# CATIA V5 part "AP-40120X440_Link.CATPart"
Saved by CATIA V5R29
Part number: AP-40120X440_Link
Bounding box of the stored display mesh (mm): x -220 to 220, y -60 to 60, z -20 to 20
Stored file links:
  C:\Users\Administrator\Desktop\프로젝트\Boxfold\AP-40120X440_Link.CATPart
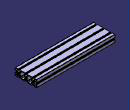
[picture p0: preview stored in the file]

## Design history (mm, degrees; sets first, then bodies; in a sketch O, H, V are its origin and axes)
Body1 (main body)
  Sketch1 on yz-plane, origin (0, 0, 0), H (0, 1, 0), V (0, 0, 1)
    point P1 (-60, -19)
    circle A1 centre (53.5, -13.5) radius 4
    circle A2 centre (53.5, 13.5) radius 4
    circle A3 centre (-53.5, -13.5) radius 4
    circle A4 centre (-53.5, 13.5) radius 4
    arc A5 centre (-38.0088, -3.1185) radius 0.3 from (-37.7966, -2.9064) to (-38.1702, -2.8656) ccw
    line L1 (-37.7966, -2.9064) -> (-37.1018, -3.6012)
    arc A6 centre (-36.8897, -3.3891) radius 0.3 from (-37.1018, -3.6012) to (-36.6868, -3.6101) ccw
    arc A7 centre (-40, 0) radius 4.9 from (-36.6868, -3.6101) to (-36.3857, -3.3086) ccw
    arc A8 centre (-36.607, -3.106) radius 0.3 from (-36.3857, -3.3086) to (-36.3949, -2.8939) ccw
    line L2 (-36.3949, -2.8939) -> (-37.0904, -2.1983)
    arc A9 centre (-36.8783, -1.9862) radius 0.3 from (-37.1314, -1.8252) to (-37.0904, -2.1983) ccw
    arc A10 centre (-40, 0) radius 3.4 from (-37.1314, -1.8252) to (-37.1323, 1.8265) ccw
    arc A11 centre (-36.8792, 1.9877) radius 0.3 from (-37.0914, 2.1998) to (-37.1323, 1.8265) ccw
    line L3 (-37.0914, 2.1998) -> (-36.396, 2.8952)
    arc A12 centre (-36.6081, 3.1073) radius 0.3 from (-36.396, 2.8952) to (-36.3869, 3.31) ccw
    arc A13 centre (-40, 0) radius 4.9 from (-36.3869, 3.31) to (-36.6881, 3.6113) ccw
    arc A14 centre (-36.8909, 3.3902) radius 0.3 from (-36.6881, 3.6113) to (-37.103, 3.6024) ccw
    line L4 (-37.103, 3.6024) -> (-37.7981, 2.9073)
    arc A15 centre (-38.0102, 3.1194) radius 0.3 from (-38.1716, 2.8665) to (-37.7981, 2.9073) ccw
    arc A16 centre (-40, 0) radius 3.4 from (-38.1716, 2.8665) to (-41.8252, 2.8686) ccw
    arc A17 centre (-41.9862, 3.1217) radius 0.3 from (-42.1983, 2.9096) to (-41.8252, 2.8686) ccw
    line L5 (-42.1983, 2.9096) -> (-42.8939, 3.6051)
    arc A18 centre (-43.106, 3.393) radius 0.3 from (-42.8939, 3.6051) to (-43.3086, 3.6143) ccw
    arc A19 centre (-40, 0) radius 4.9 from (-43.3086, 3.6143) to (-43.6101, 3.3132) ccw
    arc A20 centre (-43.3891, 3.1103) radius 0.3 from (-43.6101, 3.3132) to (-43.6012, 2.8982) ccw
    line L6 (-43.6012, 2.8982) -> (-42.9064, 2.2034)
    arc A21 centre (-43.1185, 1.9912) radius 0.3 from (-42.8656, 1.8298) to (-42.9064, 2.2034) ccw
    arc A22 centre (-40, 0) radius 3.4 from (-42.8656, 1.8298) to (-42.8665, -1.8284) ccw
    arc A23 centre (-43.1194, -1.9898) radius 0.3 from (-42.9073, -2.2019) to (-42.8665, -1.8284) ccw
    line L7 (-42.9073, -2.2019) -> (-43.6024, -2.897)
    arc A24 centre (-43.3902, -3.1091) radius 0.3 from (-43.6024, -2.897) to (-43.6113, -3.3119) ccw
    arc A25 centre (-40, 0) radius 4.9 from (-43.6113, -3.3119) to (-43.31, -3.6131) ccw
    arc A26 centre (-43.1073, -3.3919) radius 0.3 from (-43.31, -3.6131) to (-42.8952, -3.604) ccw
    line L8 (-42.8952, -3.604) -> (-42.1998, -2.9086)
    arc A27 centre (-41.9877, -3.1208) radius 0.3 from (-41.8265, -2.8677) to (-42.1998, -2.9086) ccw
    arc A28 centre (-40, 0) radius 3.4 from (-41.8265, -2.8677) to (-38.1702, -2.8656) ccw
    line L9 (39.6951, 6.0049) -> (40, 5.7)
    line L10 (40, 5.7) -> (40.3049, 6.0049)
    arc A29 centre (40, 15.5) radius 9.5 from (40.3049, 6.0049) to (47.0734, 9.1583) ccw
    arc A30 centre (46.85, 9.3585) radius 0.3 from (47.0734, 9.1583) to (47.15, 9.3585) ccw
    line L11 (47.15, 9.3585) -> (47.15, 15.7)
    arc A31 centre (46.85, 15.7) radius 0.3 from (47.15, 15.7) to (46.85, 16) ccw
    line L12 (46.85, 16) -> (44.65, 16)
    arc A32 centre (44.65, 16.5) radius 0.5 from (44.15, 16.5) to (44.65, 16) ccw
    line L13 (44.15, 16.5) -> (44.15, 19.5)
    arc A33 centre (44.65, 19.5) radius 0.5 from (44.65, 20) to (44.15, 19.5) ccw
    line L14 (44.65, 20) -> (59, 20)
    arc A34 centre (59, 19) radius 1 from (60, 19) to (59, 20) ccw
    line L15 (60, 19) -> (60, 4.65)
    arc A35 centre (59.5, 4.65) radius 0.5 from (59.5, 4.15) to (60, 4.65) ccw
    line L16 (59.5, 4.15) -> (56.5, 4.15)
    arc A36 centre (56.5, 4.65) radius 0.5 from (56, 4.65) to (56.5, 4.15) ccw
    line L17 (56, 4.65) -> (56, 6.85)
    arc A37 centre (55.7, 6.85) radius 0.3 from (56, 6.85) to (55.7, 7.15) ccw
    line L18 (55.7, 7.15) -> (49.3585, 7.15)
    arc A38 centre (49.3585, 6.85) radius 0.3 from (49.3585, 7.15) to (49.1583, 7.0734) ccw
    arc A39 centre (55.5, 0) radius 9.5 from (49.1583, 7.0734) to (46.0049, 0.3049) ccw
    line L19 (46.0049, 0.3049) -> (45.7, 0)
    line L20 (45.7, 0) -> (46.0049, -0.3049)
    arc A40 centre (55.5, 0) radius 9.5 from (46.0049, -0.3049) to (49.1583, -7.0734) ccw
    arc A41 centre (49.3585, -6.85) radius 0.3 from (49.1583, -7.0734) to (49.3585, -7.15) ccw
    line L21 (49.3585, -7.15) -> (55.7, -7.15)
    arc A42 centre (55.7, -6.85) radius 0.3 from (55.7, -7.15) to (56, -6.85) ccw
    line L22 (56, -6.85) -> (56, -4.65)
    arc A43 centre (56.5, -4.65) radius 0.5 from (56.5, -4.15) to (56, -4.65) ccw
    line L23 (56.5, -4.15) -> (59.5, -4.15)
    arc A44 centre (59.5, -4.65) radius 0.5 from (60, -4.65) to (59.5, -4.15) ccw
    line L24 (60, -4.65) -> (60, -19)
    arc A45 centre (59, -19) radius 1 from (59, -20) to (60, -19) ccw
    line L25 (59, -20) -> (44.65, -20)
    arc A46 centre (44.65, -19.5) radius 0.5 from (44.15, -19.5) to (44.65, -20) ccw
    line L26 (44.15, -19.5) -> (44.15, -16.5)
    arc A47 centre (44.65, -16.5) radius 0.5 from (44.65, -16) to (44.15, -16.5) ccw
    line L27 (44.65, -16) -> (46.85, -16)
    arc A48 centre (46.85, -15.7) radius 0.3 from (46.85, -16) to (47.15, -15.7) ccw
    line L28 (47.15, -15.7) -> (47.15, -9.3585)
    arc A49 centre (46.85, -9.3585) radius 0.3 from (47.15, -9.3585) to (47.0734, -9.1583) ccw
    arc A50 centre (40, -15.5) radius 9.5 from (47.0734, -9.1583) to (40.3049, -6.0049) ccw
    line L29 (40.3049, -6.0049) -> (40, -5.7)
    line L30 (40, -5.7) -> (39.6951, -6.0049)
    arc A51 centre (40, -15.5) radius 9.5 from (39.6951, -6.0049) to (32.9266, -9.1583) ccw
    arc A52 centre (33.15, -9.3585) radius 0.3 from (32.9266, -9.1583) to (32.85, -9.3585) ccw
    line L31 (32.85, -9.3585) -> (32.85, -15.7)
    arc A53 centre (33.15, -15.7) radius 0.3 from (32.85, -15.7) to (33.15, -16) ccw
    line L32 (33.15, -16) -> (35.35, -16)
    arc A54 centre (35.35, -16.5) radius 0.5 from (35.85, -16.5) to (35.35, -16) ccw
    line L33 (35.85, -16.5) -> (35.85, -19.5)
    arc A55 centre (35.35, -19.5) radius 0.5 from (35.35, -20) to (35.85, -19.5) ccw
    line L34 (35.35, -20) -> (4.65, -20)
    arc A56 centre (4.65, -19.5) radius 0.5 from (4.15, -19.5) to (4.65, -20) ccw
    line L35 (4.15, -19.5) -> (4.15, -16.5)
    arc A57 centre (4.65, -16.5) radius 0.5 from (4.65, -16) to (4.15, -16.5) ccw
    line L36 (4.65, -16) -> (6.85, -16)
    arc A58 centre (6.85, -15.7) radius 0.3 from (6.85, -16) to (7.15, -15.7) ccw
    line L37 (7.15, -15.7) -> (7.15, -9.3585)
    arc A59 centre (6.85, -9.3585) radius 0.3 from (7.15, -9.3585) to (7.0734, -9.1583) ccw
    arc A60 centre (0, -15.5) radius 9.5 from (7.0734, -9.1583) to (0.3049, -6.0049) ccw
    line L38 (0.3049, -6.0049) -> (0, -5.7)
    line L39 (0, -5.7) -> (-0.3049, -6.0049)
    arc A61 centre (0, -15.5) radius 9.5 from (-0.3049, -6.0049) to (-7.0734, -9.1583) ccw
    arc A62 centre (-6.85, -9.3585) radius 0.3 from (-7.0734, -9.1583) to (-7.15, -9.3585) ccw
    line L40 (-7.15, -9.3585) -> (-7.15, -15.7)
    arc A63 centre (-6.85, -15.7) radius 0.3 from (-7.15, -15.7) to (-6.85, -16) ccw
    line L41 (-6.85, -16) -> (-4.65, -16)
    arc A64 centre (-4.65, -16.5) radius 0.5 from (-4.15, -16.5) to (-4.65, -16) ccw
    line L42 (-4.15, -16.5) -> (-4.15, -19.5)
    arc A65 centre (-4.65, -19.5) radius 0.5 from (-4.65, -20) to (-4.15, -19.5) ccw
    line L43 (-4.65, -20) -> (-35.35, -20)
    arc A66 centre (-35.35, -19.5) radius 0.5 from (-35.85, -19.5) to (-35.35, -20) ccw
    line L44 (-35.85, -19.5) -> (-35.85, -16.5)
    arc A67 centre (-35.35, -16.5) radius 0.5 from (-35.35, -16) to (-35.85, -16.5) ccw
    line L45 (-35.35, -16) -> (-33.15, -16)
    arc A68 centre (-33.15, -15.7) radius 0.3 from (-33.15, -16) to (-32.85, -15.7) ccw
    line L46 (-32.85, -15.7) -> (-32.85, -9.3585)
    arc A69 centre (-33.15, -9.3585) radius 0.3 from (-32.85, -9.3585) to (-32.9266, -9.1583) ccw
    arc A70 centre (-40, -15.5) radius 9.5 from (-32.9266, -9.1583) to (-39.6951, -6.0049) ccw
    line L47 (-39.6951, -6.0049) -> (-40, -5.7)
    line L48 (-40, -5.7) -> (-40.3049, -6.0049)
    arc A71 centre (-40, -15.5) radius 9.5 from (-40.3049, -6.0049) to (-47.0734, -9.1583) ccw
    arc A72 centre (-46.85, -9.3585) radius 0.3 from (-47.0734, -9.1583) to (-47.15, -9.3585) ccw
    line L49 (-47.15, -9.3585) -> (-47.15, -15.7)
    arc A73 centre (-46.85, -15.7) radius 0.3 from (-47.15, -15.7) to (-46.85, -16) ccw
    line L50 (-46.85, -16) -> (-44.65, -16)
    arc A74 centre (-44.65, -16.5) radius 0.5 from (-44.15, -16.5) to (-44.65, -16) ccw
    line L51 (-44.15, -16.5) -> (-44.15, -19.5)
    arc A75 centre (-44.65, -19.5) radius 0.5 from (-44.65, -20) to (-44.15, -19.5) ccw
    line L52 (-44.65, -20) -> (-58, -20)
    line L53 (-58, -20) -> (-59, -20)
    arc A76 centre (-59, -19) radius 1 from (-60, -19) to (-59, -20) ccw
    line L54 (-60, -19) -> (-60, -4.65)
    arc A77 centre (-59.5, -4.65) radius 0.5 from (-59.5, -4.15) to (-60, -4.65) ccw
    line L55 (-59.5, -4.15) -> (-56.5, -4.15)
    arc A78 centre (-56.5, -4.65) radius 0.5 from (-56, -4.65) to (-56.5, -4.15) ccw
    line L56 (-56, -4.65) -> (-56, -6.85)
    arc A79 centre (-55.7, -6.85) radius 0.3 from (-56, -6.85) to (-55.7, -7.15) ccw
    line L57 (-55.7, -7.15) -> (-49.3585, -7.15)
    arc A80 centre (-49.3585, -6.85) radius 0.3 from (-49.3585, -7.15) to (-49.1583, -7.0734) ccw
    arc A81 centre (-55.5, 0) radius 9.5 from (-49.1583, -7.0734) to (-46.0049, -0.3049) ccw
    line L58 (-46.0049, -0.3049) -> (-45.7, 0)
    line L59 (-45.7, 0) -> (-46.0049, 0.3049)
    arc A82 centre (-55.5, 0) radius 9.5 from (-46.0049, 0.3049) to (-49.1583, 7.0734) ccw
    arc A83 centre (-49.3585, 6.85) radius 0.3 from (-49.1583, 7.0734) to (-49.3585, 7.15) ccw
    line L60 (-49.3585, 7.15) -> (-55.7, 7.15)
    arc A84 centre (-55.7, 6.85) radius 0.3 from (-55.7, 7.15) to (-56, 6.85) ccw
    line L61 (-56, 6.85) -> (-56, 4.65)
    arc A85 centre (-56.5, 4.65) radius 0.5 from (-56.5, 4.15) to (-56, 4.65) ccw
    line L62 (-56.5, 4.15) -> (-59.5, 4.15)
    arc A86 centre (-59.5, 4.65) radius 0.5 from (-60, 4.65) to (-59.5, 4.15) ccw
    line L63 (-60, 4.65) -> (-60, 19)
    arc A87 centre (-59, 19) radius 1 from (-59, 20) to (-60, 19) ccw
    line L64 (-59, 20) -> (-58, 20)
    line L65 (-58, 20) -> (-44.65, 20)
    arc A88 centre (-44.65, 19.5) radius 0.5 from (-44.15, 19.5) to (-44.65, 20) ccw
    line L66 (-44.15, 19.5) -> (-44.15, 16.5)
    arc A89 centre (-44.65, 16.5) radius 0.5 from (-44.65, 16) to (-44.15, 16.5) ccw
    line L67 (-44.65, 16) -> (-46.85, 16)
    arc A90 centre (-46.85, 15.7) radius 0.3 from (-46.85, 16) to (-47.15, 15.7) ccw
    line L68 (-47.15, 15.7) -> (-47.15, 9.3585)
    arc A91 centre (-46.85, 9.3585) radius 0.3 from (-47.15, 9.3585) to (-47.0734, 9.1583) ccw
    arc A92 centre (-40, 15.5) radius 9.5 from (-47.0734, 9.1583) to (-40.3049, 6.0049) ccw
    line L69 (-40.3049, 6.0049) -> (-40, 5.7)
    line L70 (-40, 5.7) -> (-39.6951, 6.0049)
    arc A93 centre (-40, 15.5) radius 9.5 from (-39.6951, 6.0049) to (-32.9266, 9.1583) ccw
    arc A94 centre (-33.15, 9.3585) radius 0.3 from (-32.9266, 9.1583) to (-32.85, 9.3585) ccw
    line L71 (-32.85, 9.3585) -> (-32.85, 15.7)
    arc A95 centre (-33.15, 15.7) radius 0.3 from (-32.85, 15.7) to (-33.15, 16) ccw
    line L72 (-33.15, 16) -> (-35.35, 16)
    arc A96 centre (-35.35, 16.5) radius 0.5 from (-35.85, 16.5) to (-35.35, 16) ccw
    line L73 (-35.85, 16.5) -> (-35.85, 19.5)
    arc A97 centre (-35.35, 19.5) radius 0.5 from (-35.35, 20) to (-35.85, 19.5) ccw
    line L74 (-35.35, 20) -> (-4.65, 20)
    arc A98 centre (-4.65, 19.5) radius 0.5 from (-4.15, 19.5) to (-4.65, 20) ccw
    line L75 (-4.15, 19.5) -> (-4.15, 16.5)
    arc A99 centre (-4.65, 16.5) radius 0.5 from (-4.65, 16) to (-4.15, 16.5) ccw
    line L76 (-4.65, 16) -> (-6.85, 16)
    arc A100 centre (-6.85, 15.7) radius 0.3 from (-6.85, 16) to (-7.15, 15.7) ccw
    line L77 (-7.15, 15.7) -> (-7.15, 9.3585)
    arc A101 centre (-6.85, 9.3585) radius 0.3 from (-7.15, 9.3585) to (-7.0734, 9.1583) ccw
    arc A102 centre (0, 15.5) radius 9.5 from (-7.0734, 9.1583) to (-0.3049, 6.0049) ccw
    line L78 (-0.3049, 6.0049) -> (0, 5.7)
    line L79 (0, 5.7) -> (0.3049, 6.0049)
    arc A103 centre (0, 15.5) radius 9.5 from (0.3049, 6.0049) to (7.0734, 9.1583) ccw
    arc A104 centre (6.85, 9.3585) radius 0.3 from (7.0734, 9.1583) to (7.15, 9.3585) ccw
    line L80 (7.15, 9.3585) -> (7.15, 15.7)
    arc A105 centre (6.85, 15.7) radius 0.3 from (7.15, 15.7) to (6.85, 16) ccw
    line L81 (6.85, 16) -> (4.65, 16)
    arc A106 centre (4.65, 16.5) radius 0.5 from (4.15, 16.5) to (4.65, 16) ccw
    line L82 (4.15, 16.5) -> (4.15, 19.5)
    arc A107 centre (4.65, 19.5) radius 0.5 from (4.65, 20) to (4.15, 19.5) ccw
    line L83 (4.65, 20) -> (35.35, 20)
    arc A108 centre (35.35, 19.5) radius 0.5 from (35.85, 19.5) to (35.35, 20) ccw
    line L84 (35.85, 19.5) -> (35.85, 16.5)
    arc A109 centre (35.35, 16.5) radius 0.5 from (35.35, 16) to (35.85, 16.5) ccw
    line L85 (35.35, 16) -> (33.15, 16)
    arc A110 centre (33.15, 15.7) radius 0.3 from (33.15, 16) to (32.85, 15.7) ccw
    line L86 (32.85, 15.7) -> (32.85, 9.3585)
    arc A111 centre (33.15, 9.3585) radius 0.3 from (32.85, 9.3585) to (32.9266, 9.1583) ccw
    arc A112 centre (40, 15.5) radius 9.5 from (32.9266, 9.1583) to (39.6951, 6.0049) ccw
    arc A113 centre (13.15, -14) radius 3 from (10.15, -14) to (13.15, -17) ccw
    line L87 (13.15, -17) -> (26.85, -17)
    arc A114 centre (26.85, -14) radius 3 from (26.85, -17) to (29.85, -14) ccw
    line L88 (29.85, -14) -> (29.85, -8.9422)
    arc A115 centre (20, -0.0053) radius 13.3 from (29.85, -8.9422) to (29.85, 8.9315) ccw
    line L89 (29.85, 8.9315) -> (29.85, 14)
    arc A116 centre (26.85, 14) radius 3 from (29.85, 14) to (26.85, 17) ccw
    line L90 (26.85, 17) -> (13.15, 17)
    arc A117 centre (13.15, 14) radius 3 from (13.15, 17) to (10.15, 14) ccw
    line L91 (10.15, 14) -> (10.15, 8.9315)
    arc A118 centre (20, -0.0053) radius 13.3 from (10.15, 8.9315) to (10.15, -8.9422) ccw
    line L92 (10.15, -8.9422) -> (10.15, -14)
    arc A119 centre (1.9912, -3.1185) radius 0.3 from (2.2034, -2.9064) to (1.8298, -2.8656) ccw
    line L93 (2.2034, -2.9064) -> (2.8982, -3.6012)
    arc A120 centre (3.1103, -3.3891) radius 0.3 from (2.8982, -3.6012) to (3.3132, -3.6101) ccw
    arc A121 centre (0, 0) radius 4.9 from (3.3132, -3.6101) to (3.6143, -3.3086) ccw
    arc A122 centre (3.393, -3.106) radius 0.3 from (3.6143, -3.3086) to (3.6051, -2.8939) ccw
    line L94 (3.6051, -2.8939) -> (2.9096, -2.1983)
    arc A123 centre (3.1217, -1.9862) radius 0.3 from (2.8686, -1.8252) to (2.9096, -2.1983) ccw
    arc A124 centre (0, 0) radius 3.4 from (2.8686, -1.8252) to (2.8677, 1.8265) ccw
    arc A125 centre (3.1208, 1.9877) radius 0.3 from (2.9086, 2.1998) to (2.8677, 1.8265) ccw
    line L95 (2.9086, 2.1998) -> (3.604, 2.8952)
    arc A126 centre (3.3919, 3.1073) radius 0.3 from (3.604, 2.8952) to (3.6131, 3.31) ccw
    arc A127 centre (0, 0) radius 4.9 from (3.6131, 3.31) to (3.3119, 3.6113) ccw
    arc A128 centre (3.1091, 3.3902) radius 0.3 from (3.3119, 3.6113) to (2.897, 3.6024) ccw
    line L96 (2.897, 3.6024) -> (2.2019, 2.9073)
    arc A129 centre (1.9898, 3.1194) radius 0.3 from (1.8284, 2.8665) to (2.2019, 2.9073) ccw
    arc A130 centre (0, 0) radius 3.4 from (1.8284, 2.8665) to (-1.8252, 2.8686) ccw
    arc A131 centre (-1.9862, 3.1217) radius 0.3 from (-2.1983, 2.9096) to (-1.8252, 2.8686) ccw
    line L97 (-2.1983, 2.9096) -> (-2.8939, 3.6051)
    arc A132 centre (-3.106, 3.393) radius 0.3 from (-2.8939, 3.6051) to (-3.3086, 3.6143) ccw
    arc A133 centre (0, 0) radius 4.9 from (-3.3086, 3.6143) to (-3.6101, 3.3132) ccw
    arc A134 centre (-3.3891, 3.1103) radius 0.3 from (-3.6101, 3.3132) to (-3.6012, 2.8982) ccw
    line L98 (-3.6012, 2.8982) -> (-2.9064, 2.2034)
    arc A135 centre (-3.1185, 1.9912) radius 0.3 from (-2.8656, 1.8298) to (-2.9064, 2.2034) ccw
    arc A136 centre (0, 0) radius 3.4 from (-2.8656, 1.8298) to (-2.8665, -1.8284) ccw
    arc A137 centre (-3.1194, -1.9898) radius 0.3 from (-2.9073, -2.2019) to (-2.8665, -1.8284) ccw
    line L99 (-2.9073, -2.2019) -> (-3.6024, -2.897)
    arc A138 centre (-3.3902, -3.1091) radius 0.3 from (-3.6024, -2.897) to (-3.6113, -3.3119) ccw
    arc A139 centre (0, 0) radius 4.9 from (-3.6113, -3.3119) to (-3.31, -3.6131) ccw
    arc A140 centre (-3.1073, -3.3919) radius 0.3 from (-3.31, -3.6131) to (-2.8952, -3.604) ccw
    line L100 (-2.8952, -3.604) -> (-2.1998, -2.9086)
    arc A141 centre (-1.9877, -3.1208) radius 0.3 from (-1.8265, -2.8677) to (-2.1998, -2.9086) ccw
    arc A142 centre (0, 0) radius 3.4 from (-1.8265, -2.8677) to (1.8298, -2.8656) ccw
    arc A143 centre (41.9912, -3.1185) radius 0.3 from (42.2034, -2.9064) to (41.8298, -2.8656) ccw
    line L101 (42.2034, -2.9064) -> (42.8982, -3.6012)
    arc A144 centre (43.1103, -3.3891) radius 0.3 from (42.8982, -3.6012) to (43.3132, -3.6101) ccw
    arc A145 centre (40, 0) radius 4.9 from (43.3132, -3.6101) to (43.6143, -3.3086) ccw
    arc A146 centre (43.393, -3.106) radius 0.3 from (43.6143, -3.3086) to (43.6051, -2.8939) ccw
    line L102 (43.6051, -2.8939) -> (42.9096, -2.1983)
    arc A147 centre (43.1217, -1.9862) radius 0.3 from (42.8686, -1.8252) to (42.9096, -2.1983) ccw
    arc A148 centre (40, 0) radius 3.4 from (42.8686, -1.8252) to (42.8677, 1.8265) ccw
    arc A149 centre (43.1208, 1.9877) radius 0.3 from (42.9086, 2.1998) to (42.8677, 1.8265) ccw
    line L103 (42.9086, 2.1998) -> (43.604, 2.8952)
    arc A150 centre (43.3919, 3.1073) radius 0.3 from (43.604, 2.8952) to (43.6131, 3.31) ccw
    arc A151 centre (40, 0) radius 4.9 from (43.6131, 3.31) to (43.3119, 3.6113) ccw
    arc A152 centre (43.1091, 3.3902) radius 0.3 from (43.3119, 3.6113) to (42.897, 3.6024) ccw
    line L104 (42.897, 3.6024) -> (42.2019, 2.9073)
    arc A153 centre (41.9898, 3.1194) radius 0.3 from (41.8284, 2.8665) to (42.2019, 2.9073) ccw
    arc A154 centre (40, 0) radius 3.4 from (41.8284, 2.8665) to (38.1748, 2.8686) ccw
    arc A155 centre (38.0138, 3.1217) radius 0.3 from (37.8017, 2.9096) to (38.1748, 2.8686) ccw
    line L105 (37.8017, 2.9096) -> (37.1061, 3.6051)
    arc A156 centre (36.894, 3.393) radius 0.3 from (37.1061, 3.6051) to (36.6914, 3.6143) ccw
    arc A157 centre (40, 0) radius 4.9 from (36.6914, 3.6143) to (36.3899, 3.3132) ccw
    arc A158 centre (36.6109, 3.1103) radius 0.3 from (36.3899, 3.3132) to (36.3988, 2.8982) ccw
    line L106 (36.3988, 2.8982) -> (37.0936, 2.2034)
    arc A159 centre (36.8815, 1.9912) radius 0.3 from (37.1344, 1.8298) to (37.0936, 2.2034) ccw
    arc A160 centre (40, 0) radius 3.4 from (37.1344, 1.8298) to (37.1335, -1.8284) ccw
    arc A161 centre (36.8806, -1.9898) radius 0.3 from (37.0927, -2.2019) to (37.1335, -1.8284) ccw
    line L107 (37.0927, -2.2019) -> (36.3976, -2.897)
    arc A162 centre (36.6098, -3.1091) radius 0.3 from (36.3976, -2.897) to (36.3887, -3.3119) ccw
    arc A163 centre (40, 0) radius 4.9 from (36.3887, -3.3119) to (36.69, -3.6131) ccw
    arc A164 centre (36.8927, -3.3919) radius 0.3 from (36.69, -3.6131) to (37.1048, -3.604) ccw
    line L108 (37.1048, -3.604) -> (37.8002, -2.9086)
    arc A165 centre (38.0123, -3.1208) radius 0.3 from (38.1735, -2.8677) to (37.8002, -2.9086) ccw
    arc A166 centre (40, 0) radius 3.4 from (38.1735, -2.8677) to (41.8298, -2.8656) ccw
    line L109 (-13.15, 17) -> (-26.85, 17)
    arc A167 centre (-26.85, 14) radius 3 from (-26.85, 17) to (-29.85, 14) ccw
    line L110 (-29.85, 14) -> (-29.85, 8.9315)
    arc A168 centre (-20, -0.0053) radius 13.3 from (-29.85, 8.9315) to (-29.85, -8.9422) ccw
    line L111 (-29.85, -8.9422) -> (-29.85, -14)
    arc A169 centre (-26.85, -14) radius 3 from (-29.85, -14) to (-26.85, -17) ccw
    line L112 (-26.85, -17) -> (-13.15, -17)
    arc A170 centre (-13.15, -14) radius 3 from (-13.15, -17) to (-10.15, -14) ccw
    line L113 (-10.15, -14) -> (-10.15, -8.9422)
    arc A171 centre (-20, -0.0053) radius 13.3 from (-10.15, -8.9422) to (-10.15, 8.9315) ccw
    line L114 (-10.15, 8.9315) -> (-10.15, 14)
    arc A172 centre (-13.15, 14) radius 3 from (-10.15, 14) to (-13.15, 17) ccw
    point P2 (-37.7966, -2.9064)
    point P3 (-38.1702, -2.8656)
    point P4 (-37.7966, -2.9064)
    point P5 (-37.1018, -3.6012)
    point P6 (-37.1018, -3.6012)
    point P7 (-36.6868, -3.6101)
    point P8 (-36.6868, -3.6101)
    point P9 (-36.3857, -3.3086)
    point P10 (-36.3857, -3.3086)
    point P11 (-36.3949, -2.8939)
    point P12 (-36.3949, -2.8939)
    point P13 (-37.0904, -2.1983)
    point P14 (-37.1314, -1.8252)
    point P15 (-37.0904, -2.1983)
    point P16 (-37.1314, -1.8252)
    point P17 (-37.1323, 1.8265)
    point P18 (-37.0914, 2.1998)
    point P19 (-37.1323, 1.8265)
    point P20 (-37.0914, 2.1998)
    point P21 (-36.396, 2.8952)
    point P22 (-36.396, 2.8952)
    point P23 (-36.3869, 3.31)
    point P24 (-36.3869, 3.31)
    point P25 (-36.6881, 3.6113)
    point P26 (-36.6881, 3.6113)
    point P27 (-37.103, 3.6024)
    point P28 (-37.103, 3.6024)
    point P29 (-37.7981, 2.9073)
    point P30 (-38.1716, 2.8665)
    point P31 (-37.7981, 2.9073)
    point P32 (-38.1716, 2.8665)
    point P33 (-41.8252, 2.8686)
    point P34 (-42.1983, 2.9096)
    point P35 (-41.8252, 2.8686)
    point P36 (-42.1983, 2.9096)
    point P37 (-42.8939, 3.6051)
    point P38 (-42.8939, 3.6051)
    point P39 (-43.3086, 3.6143)
    point P40 (-43.3086, 3.6143)
    point P41 (-43.6101, 3.3132)
    point P42 (-43.6101, 3.3132)
    point P43 (-43.6012, 2.8982)
    point P44 (-43.6012, 2.8982)
    point P45 (-42.9064, 2.2034)
    point P46 (-42.8656, 1.8298)
    point P47 (-42.9064, 2.2034)
    point P48 (-42.8656, 1.8298)
    point P49 (-42.8665, -1.8284)
    point P50 (-42.9073, -2.2019)
    point P51 (-42.8665, -1.8284)
    point P52 (-42.9073, -2.2019)
    point P53 (-43.6024, -2.897)
    point P54 (-43.6024, -2.897)
    point P55 (-43.6113, -3.3119)
    point P56 (-43.6113, -3.3119)
    point P57 (-43.31, -3.6131)
    point P58 (-43.31, -3.6131)
    point P59 (-42.8952, -3.604)
    point P60 (-42.8952, -3.604)
    point P61 (-42.1998, -2.9086)
    point P62 (-41.8265, -2.8677)
    point P63 (-42.1998, -2.9086)
    point P64 (-41.8265, -2.8677)
    point P65 (-38.1702, -2.8656)
    point P66 (39.6951, 6.0049)
    point P67 (40, 5.7)
    point P68 (40, 5.7)
    point P69 (40.3049, 6.0049)
    point P70 (40.3049, 6.0049)
    point P71 (47.0734, 9.1583)
    point P72 (47.0734, 9.1583)
    point P73 (47.15, 9.3585)
    point P74 (47.15, 9.3585)
    point P75 (47.15, 15.7)
    point P76 (47.15, 15.7)
    point P77 (46.85, 16)
    point P78 (46.85, 16)
    point P79 (44.65, 16)
    point P80 (44.15, 16.5)
    point P81 (44.65, 16)
    point P82 (44.15, 16.5)
    point P83 (44.15, 19.5)
    point P84 (44.65, 20)
    point P85 (44.15, 19.5)
    point P86 (44.65, 20)
    point P87 (59, 20)
    point P88 (60, 19)
    point P89 (59, 20)
    point P90 (60, 19)
    point P91 (60, 4.65)
    point P92 (59.5, 4.15)
    point P93 (60, 4.65)
    point P94 (59.5, 4.15)
    point P95 (56.5, 4.15)
    point P96 (56, 4.65)
    point P97 (56.5, 4.15)
    point P98 (56, 4.65)
    point P99 (56, 6.85)
    point P100 (56, 6.85)
    point P101 (55.7, 7.15)
    point P102 (55.7, 7.15)
    point P103 (49.3585, 7.15)
    point P104 (49.3585, 7.15)
    point P105 (49.1583, 7.0734)
    point P106 (49.1583, 7.0734)
    point P107 (46.0049, 0.3049)
    point P108 (46.0049, 0.3049)
    point P109 (45.7, 0)
    point P110 (45.7, 0)
    point P111 (46.0049, -0.3049)
    point P112 (46.0049, -0.3049)
    point P113 (49.1583, -7.0734)
    point P114 (49.1583, -7.0734)
    point P115 (49.3585, -7.15)
    point P116 (49.3585, -7.15)
    point P117 (55.7, -7.15)
    point P118 (55.7, -7.15)
    point P119 (56, -6.85)
    point P120 (56, -6.85)
    point P121 (56, -4.65)
    point P122 (56.5, -4.15)
    point P123 (56, -4.65)
    point P124 (56.5, -4.15)
    point P125 (59.5, -4.15)
    point P126 (60, -4.65)
    point P127 (59.5, -4.15)
    point P128 (60, -4.65)
    point P129 (60, -19)
    point P130 (59, -20)
    point P131 (60, -19)
    point P132 (59, -20)
    point P133 (44.65, -20)
    point P134 (44.15, -19.5)
    point P135 (44.65, -20)
    point P136 (44.15, -19.5)
    point P137 (44.15, -16.5)
    point P138 (44.65, -16)
    point P139 (44.15, -16.5)
    point P140 (44.65, -16)
    point P141 (46.85, -16)
    point P142 (46.85, -16)
    point P143 (47.15, -15.7)
    point P144 (47.15, -15.7)
    point P145 (47.15, -9.3585)
    point P146 (47.15, -9.3585)
    point P147 (47.0734, -9.1583)
    point P148 (47.0734, -9.1583)
    point P149 (40.3049, -6.0049)
    point P150 (40.3049, -6.0049)
    point P151 (40, -5.7)
    point P152 (40, -5.7)
    point P153 (39.6951, -6.0049)
    point P154 (39.6951, -6.0049)
    point P155 (32.9266, -9.1583)
    point P156 (32.9266, -9.1583)
    point P157 (32.85, -9.3585)
    point P158 (32.85, -9.3585)
    point P159 (32.85, -15.7)
    point P160 (32.85, -15.7)
    point P161 (33.15, -16)
    point P162 (33.15, -16)
    point P163 (35.35, -16)
    point P164 (35.85, -16.5)
    point P165 (35.35, -16)
    point P166 (35.85, -16.5)
    point P167 (35.85, -19.5)
    point P168 (35.35, -20)
    point P169 (35.85, -19.5)
    point P170 (35.35, -20)
    point P171 (4.65, -20)
    point P172 (4.15, -19.5)
    point P173 (4.65, -20)
    point P174 (4.15, -19.5)
    point P175 (4.15, -16.5)
    point P176 (4.65, -16)
    point P177 (4.15, -16.5)
    point P178 (4.65, -16)
    point P179 (6.85, -16)
    point P180 (6.85, -16)
    point P181 (7.15, -15.7)
    point P182 (7.15, -15.7)
    point P183 (7.15, -9.3585)
    point P184 (7.15, -9.3585)
    point P185 (7.0734, -9.1583)
    point P186 (7.0734, -9.1583)
    point P187 (0.3049, -6.0049)
    point P188 (0.3049, -6.0049)
    point P189 (0, -5.7)
    point P190 (0, -5.7)
    point P191 (-0.3049, -6.0049)
    point P192 (-0.3049, -6.0049)
    point P193 (-7.0734, -9.1583)
    point P194 (-7.0734, -9.1583)
    point P195 (-7.15, -9.3585)
    point P196 (-7.15, -9.3585)
    point P197 (-7.15, -15.7)
    point P198 (-7.15, -15.7)
    point P199 (-6.85, -16)
    point P200 (-6.85, -16)
    point P201 (-4.65, -16)
    point P202 (-4.15, -16.5)
    point P203 (-4.65, -16)
    point P204 (-4.15, -16.5)
    point P205 (-4.15, -19.5)
    point P206 (-4.65, -20)
    point P207 (-4.15, -19.5)
    point P208 (-4.65, -20)
    point P209 (-35.35, -20)
    point P210 (-35.85, -19.5)
    point P211 (-35.35, -20)
    point P212 (-35.85, -19.5)
    point P213 (-35.85, -16.5)
    point P214 (-35.35, -16)
    point P215 (-35.85, -16.5)
    point P216 (-35.35, -16)
    point P217 (-33.15, -16)
    point P218 (-33.15, -16)
    point P219 (-32.85, -15.7)
    point P220 (-32.85, -15.7)
    point P221 (-32.85, -9.3585)
    point P222 (-32.85, -9.3585)
    point P223 (-32.9266, -9.1583)
    point P224 (-32.9266, -9.1583)
    point P225 (-39.6951, -6.0049)
    point P226 (-39.6951, -6.0049)
    point P227 (-40, -5.7)
    point P228 (-40, -5.7)
    point P229 (-40.3049, -6.0049)
    point P230 (-40.3049, -6.0049)
    point P231 (-47.0734, -9.1583)
    point P232 (-47.0734, -9.1583)
    point P233 (-47.15, -9.3585)
    point P234 (-47.15, -9.3585)
    point P235 (-47.15, -15.7)
    point P236 (-47.15, -15.7)
    point P237 (-46.85, -16)
    point P238 (-46.85, -16)
    point P239 (-44.65, -16)
    point P240 (-44.15, -16.5)
    point P241 (-44.65, -16)
    point P242 (-44.15, -16.5)
    point P243 (-44.15, -19.5)
    point P244 (-44.65, -20)
    point P245 (-44.15, -19.5)
    point P246 (-44.65, -20)
    point P247 (-58, -20)
    point P248 (-58, -20)
    point P249 (-59, -20)
    point P250 (-60, -19)
    point P251 (-59, -20)
    point P252 (-60, -19)
    point P253 (-60, -4.65)
    point P254 (-59.5, -4.15)
    point P255 (-60, -4.65)
    point P256 (-59.5, -4.15)
    point P257 (-56.5, -4.15)
    point P258 (-56, -4.65)
    point P259 (-56.5, -4.15)
    point P260 (-56, -4.65)
    point P261 (-56, -6.85)
    point P262 (-56, -6.85)
    point P263 (-55.7, -7.15)
    point P264 (-55.7, -7.15)
    point P265 (-49.3585, -7.15)
    point P266 (-49.3585, -7.15)
    point P267 (-49.1583, -7.0734)
    point P268 (-49.1583, -7.0734)
    point P269 (-46.0049, -0.3049)
    point P270 (-46.0049, -0.3049)
    point P271 (-45.7, 0)
    point P272 (-45.7, 0)
    point P273 (-46.0049, 0.3049)
    point P274 (-46.0049, 0.3049)
    point P275 (-49.1583, 7.0734)
    point P276 (-49.1583, 7.0734)
    point P277 (-49.3585, 7.15)
    point P278 (-49.3585, 7.15)
    point P279 (-55.7, 7.15)
    point P280 (-55.7, 7.15)
    point P281 (-56, 6.85)
    point P282 (-56, 6.85)
    point P283 (-56, 4.65)
    point P284 (-56.5, 4.15)
    point P285 (-56, 4.65)
    point P286 (-56.5, 4.15)
    point P287 (-59.5, 4.15)
    point P288 (-60, 4.65)
    point P289 (-59.5, 4.15)
    point P290 (-60, 4.65)
    point P291 (-60, 19)
    point P292 (-59, 20)
    point P293 (-60, 19)
    point P294 (-59, 20)
    point P295 (-58, 20)
    point P296 (-58, 20)
    point P297 (-44.65, 20)
    point P298 (-44.15, 19.5)
    point P299 (-44.65, 20)
    point P300 (-44.15, 19.5)
    point P301 (-44.15, 16.5)
    point P302 (-44.65, 16)
    point P303 (-44.15, 16.5)
    point P304 (-44.65, 16)
    point P305 (-46.85, 16)
    point P306 (-46.85, 16)
    point P307 (-47.15, 15.7)
    point P308 (-47.15, 15.7)
    point P309 (-47.15, 9.3585)
    point P310 (-47.15, 9.3585)
    point P311 (-47.0734, 9.1583)
    point P312 (-47.0734, 9.1583)
    point P313 (-40.3049, 6.0049)
    point P314 (-40.3049, 6.0049)
    point P315 (-40, 5.7)
    point P316 (-40, 5.7)
    point P317 (-39.6951, 6.0049)
    point P318 (-39.6951, 6.0049)
    point P319 (-32.9266, 9.1583)
    point P320 (-32.9266, 9.1583)
    point P321 (-32.85, 9.3585)
    point P322 (-32.85, 9.3585)
    point P323 (-32.85, 15.7)
    point P324 (-32.85, 15.7)
    point P325 (-33.15, 16)
    point P326 (-33.15, 16)
    point P327 (-35.35, 16)
    point P328 (-35.85, 16.5)
    point P329 (-35.35, 16)
    point P330 (-35.85, 16.5)
    point P331 (-35.85, 19.5)
    point P332 (-35.35, 20)
    point P333 (-35.85, 19.5)
    point P334 (-35.35, 20)
    point P335 (-4.65, 20)
    point P336 (-4.15, 19.5)
    point P337 (-4.65, 20)
    point P338 (-4.15, 19.5)
    point P339 (-4.15, 16.5)
    point P340 (-4.65, 16)
    point P341 (-4.15, 16.5)
    point P342 (-4.65, 16)
    point P343 (-6.85, 16)
    point P344 (-6.85, 16)
    point P345 (-7.15, 15.7)
    point P346 (-7.15, 15.7)
    point P347 (-7.15, 9.3585)
    point P348 (-7.15, 9.3585)
    point P349 (-7.0734, 9.1583)
    point P350 (-7.0734, 9.1583)
    point P351 (-0.3049, 6.0049)
    point P352 (-0.3049, 6.0049)
    point P353 (0, 5.7)
    point P354 (0, 5.7)
    point P355 (0.3049, 6.0049)
    point P356 (0.3049, 6.0049)
    point P357 (7.0734, 9.1583)
    point P358 (7.0734, 9.1583)
    point P359 (7.15, 9.3585)
    point P360 (7.15, 9.3585)
    point P361 (7.15, 15.7)
    point P362 (7.15, 15.7)
    point P363 (6.85, 16)
    point P364 (6.85, 16)
    point P365 (4.65, 16)
    point P366 (4.15, 16.5)
    point P367 (4.65, 16)
    point P368 (4.15, 16.5)
    point P369 (4.15, 19.5)
    point P370 (4.65, 20)
    point P371 (4.15, 19.5)
    point P372 (4.65, 20)
    point P373 (35.35, 20)
    point P374 (35.85, 19.5)
    point P375 (35.35, 20)
    point P376 (35.85, 19.5)
    point P377 (35.85, 16.5)
    point P378 (35.35, 16)
    point P379 (35.85, 16.5)
    point P380 (35.35, 16)
    point P381 (33.15, 16)
    point P382 (33.15, 16)
    point P383 (32.85, 15.7)
    point P384 (32.85, 15.7)
    point P385 (32.85, 9.3585)
    point P386 (32.85, 9.3585)
    point P387 (32.9266, 9.1583)
    point P388 (32.9266, 9.1583)
    point P389 (39.6951, 6.0049)
    point P390 (10.15, -14)
    point P391 (13.15, -17)
    point P392 (13.15, -17)
    point P393 (26.85, -17)
    point P394 (26.85, -17)
    point P395 (29.85, -14)
    point P396 (29.85, -14)
    point P397 (29.85, -8.9422)
    point P398 (29.85, -8.9422)
    point P399 (29.85, 8.9315)
    point P400 (29.85, 8.9315)
    point P401 (29.85, 14)
    point P402 (29.85, 14)
    point P403 (26.85, 17)
    point P404 (26.85, 17)
    point P405 (13.15, 17)
    point P406 (13.15, 17)
    point P407 (10.15, 14)
    point P408 (10.15, 14)
    point P409 (10.15, 8.9315)
    point P410 (10.15, 8.9315)
    point P411 (10.15, -8.9422)
    point P412 (10.15, -8.9422)
    point P413 (10.15, -14)
    point P414 (2.2034, -2.9064)
    point P415 (1.8298, -2.8656)
    point P416 (2.2034, -2.9064)
    point P417 (2.8982, -3.6012)
    point P418 (2.8982, -3.6012)
    point P419 (3.3132, -3.6101)
    point P420 (3.3132, -3.6101)
    point P421 (3.6143, -3.3086)
    point P422 (3.6143, -3.3086)
    point P423 (3.6051, -2.8939)
    point P424 (3.6051, -2.8939)
    point P425 (2.9096, -2.1983)
    point P426 (2.8686, -1.8252)
    point P427 (2.9096, -2.1983)
    point P428 (2.8686, -1.8252)
    point P429 (2.8677, 1.8265)
    point P430 (2.9086, 2.1998)
    point P431 (2.8677, 1.8265)
    point P432 (2.9086, 2.1998)
    point P433 (3.604, 2.8952)
    point P434 (3.604, 2.8952)
    point P435 (3.6131, 3.31)
    point P436 (3.6131, 3.31)
    point P437 (3.3119, 3.6113)
    point P438 (3.3119, 3.6113)
    point P439 (2.897, 3.6024)
    point P440 (2.897, 3.6024)
    point P441 (2.2019, 2.9073)
    point P442 (1.8284, 2.8665)
    point P443 (2.2019, 2.9073)
    point P444 (1.8284, 2.8665)
    point P445 (-1.8252, 2.8686)
    point P446 (-2.1983, 2.9096)
    point P447 (-1.8252, 2.8686)
    point P448 (-2.1983, 2.9096)
    point P449 (-2.8939, 3.6051)
    point P450 (-2.8939, 3.6051)
    point P451 (-3.3086, 3.6143)
    point P452 (-3.3086, 3.6143)
    point P453 (-3.6101, 3.3132)
    point P454 (-3.6101, 3.3132)
    point P455 (-3.6012, 2.8982)
    point P456 (-3.6012, 2.8982)
    point P457 (-2.9064, 2.2034)
    point P458 (-2.8656, 1.8298)
    point P459 (-2.9064, 2.2034)
    point P460 (-2.8656, 1.8298)
    point P461 (-2.8665, -1.8284)
    point P462 (-2.9073, -2.2019)
    point P463 (-2.8665, -1.8284)
    point P464 (-2.9073, -2.2019)
    point P465 (-3.6024, -2.897)
    point P466 (-3.6024, -2.897)
    point P467 (-3.6113, -3.3119)
    point P468 (-3.6113, -3.3119)
    point P469 (-3.31, -3.6131)
    point P470 (-3.31, -3.6131)
    point P471 (-2.8952, -3.604)
    point P472 (-2.8952, -3.604)
    point P473 (-2.1998, -2.9086)
    point P474 (-1.8265, -2.8677)
    point P475 (-2.1998, -2.9086)
    point P476 (-1.8265, -2.8677)
    point P477 (1.8298, -2.8656)
    point P478 (42.2034, -2.9064)
    point P479 (41.8298, -2.8656)
    point P480 (42.2034, -2.9064)
    point P481 (42.8982, -3.6012)
    point P482 (42.8982, -3.6012)
    point P483 (43.3132, -3.6101)
    point P484 (43.3132, -3.6101)
    point P485 (43.6143, -3.3086)
    point P486 (43.6143, -3.3086)
    point P487 (43.6051, -2.8939)
    point P488 (43.6051, -2.8939)
    point P489 (42.9096, -2.1983)
    point P490 (42.8686, -1.8252)
    point P491 (42.9096, -2.1983)
    point P492 (42.8686, -1.8252)
    point P493 (42.8677, 1.8265)
    point P494 (42.9086, 2.1998)
    point P495 (42.8677, 1.8265)
    point P496 (42.9086, 2.1998)
    point P497 (43.604, 2.8952)
    point P498 (43.604, 2.8952)
    point P499 (43.6131, 3.31)
    point P500 (43.6131, 3.31)
    point P501 (43.3119, 3.6113)
    point P502 (43.3119, 3.6113)
    point P503 (42.897, 3.6024)
    point P504 (42.897, 3.6024)
    point P505 (42.2019, 2.9073)
    point P506 (41.8284, 2.8665)
    point P507 (42.2019, 2.9073)
    point P508 (41.8284, 2.8665)
    point P509 (38.1748, 2.8686)
    point P510 (37.8017, 2.9096)
    point P511 (38.1748, 2.8686)
    point P512 (37.8017, 2.9096)
    point P513 (37.1061, 3.6051)
    point P514 (37.1061, 3.6051)
    point P515 (36.6914, 3.6143)
    point P516 (36.6914, 3.6143)
    point P517 (36.3899, 3.3132)
    point P518 (36.3899, 3.3132)
    point P519 (36.3988, 2.8982)
    point P520 (36.3988, 2.8982)
    point P521 (37.0936, 2.2034)
    point P522 (37.1344, 1.8298)
    point P523 (37.0936, 2.2034)
    point P524 (37.1344, 1.8298)
    point P525 (37.1335, -1.8284)
    point P526 (37.0927, -2.2019)
    point P527 (37.1335, -1.8284)
    point P528 (37.0927, -2.2019)
    point P529 (36.3976, -2.897)
    point P530 (36.3976, -2.897)
    point P531 (36.3887, -3.3119)
    point P532 (36.3887, -3.3119)
    point P533 (36.69, -3.6131)
    point P534 (36.69, -3.6131)
    point P535 (37.1048, -3.604)
    point P536 (37.1048, -3.604)
    point P537 (37.8002, -2.9086)
    point P538 (38.1735, -2.8677)
    point P539 (37.8002, -2.9086)
    point P540 (38.1735, -2.8677)
    point P541 (41.8298, -2.8656)
    point P542 (-13.15, 17)
    point P543 (-26.85, 17)
    point P544 (-26.85, 17)
    point P545 (-29.85, 14)
    point P546 (-29.85, 14)
    point P547 (-29.85, 8.9315)
    point P548 (-29.85, 8.9315)
    point P549 (-29.85, -8.9422)
    point P550 (-29.85, -8.9422)
    point P551 (-29.85, -14)
    point P552 (-29.85, -14)
    point P553 (-26.85, -17)
    point P554 (-26.85, -17)
    point P555 (-13.15, -17)
    point P556 (-13.15, -17)
    point P557 (-10.15, -14)
    point P558 (-10.15, -14)
    point P559 (-10.15, -8.9422)
    point P560 (-10.15, -8.9422)
    point P561 (-10.15, 8.9315)
    point P562 (-10.15, 8.9315)
    point P563 (-10.15, 14)
    point P564 (-10.15, 14)
    point P565 (-13.15, 17)
    reference intersected line E1 through (0, 0) direction (0, 1) from zx-plane
    distance H L83 = 20
    distance L15 E1 = 60
    coincidence: P2 P4, P3 P65, P5 P6, P7 P8, P9 P10, P11 P12, P13 P15, P14 P16, P17 P19, P18 P20, P21 P22, P23 P24, P25 P26, P27 P28, P29 P31, P30 P32, P33 P35, P34 P36, P37 P38, P39 P40, P41 P42, P43 P44, P45 P47, P46 P48, P49 P51, P50 P52, P53 P54, P55 P56, P57 P58, P59 P60, P61 P63, P62 P64, P66 P389, P67 P68, P69 P70, P71 P72, P73 P74, P75 P76, P77 P78, P79 P81, P80 P82, P83 P85, P84 P86, P88 P90, P89 P87, P91 P93, P92 P94, P95 P97, P96 P98, P99 P100, P101 P102, P103 P104, P105 P106, P107 P108, P109 P110, P111 P112, P113 P114, P115 P116, P117 P118, P119 P120, P121 P123, P122 P124, P125 P127, P126 P128, P132 P130, P133 P135, P134 P136, P137 P139, P138 P140, P141 P142, P143 P144, P145 P146, P147 P148, P149 P150, P151 P152, P153 P154, P155 P156, P157 P158, P159 P160, P161 P162, P163 P165, P164 P166, P167 P169, P168 P170, P171 P173, P172 P174, P175 P177, P176 P178, P179 P180, P181 P182, P183 P184, P185 P186, P187 P188, P189 P190, P191 P192, P193 P194, P195 P196, P197 P198, P199 P200, P201 P203, P202 P204, P205 P207, P206 P208, P209 P211, P210 P212, P213 P215, P214 P216, P217 P218, P219 P220, P221 P222, P223 P224, P225 P226, P227 P228, P229 P230, P231 P232, P233 P234, P235 P236, P237 P238, P239 P241, P240 P242, P243 P245, P244 P246, P247 P248, P249 P251, P250 P252, P253 P255, P254 P256, P257 P259, P258 P260, P261 P262, P263 P264, P265 P266, P267 P268, P269 P270, P271 P272, P273 P274, P275 P276, P277 P278, P279 P280, P281 P282, P283 P285, P284 P286, P287 P289, P288 P290, P291 P293, P292 P294, P295 P296, P297 P299, P298 P300, P301 P303, P302 P304, P305 P306, P307 P308, P309 P310, P311 P312, P313 P314, P315 P316, P317 P318, P319 P320, P321 P322, P323 P324, P325 P326, P327 P329, P328 P330, P331 P333, P332 P334, P335 P337, P336 P338, P339 P341, P340 P342, P343 P344, P345 P346, P347 P348, P349 P350, P351 P352, P353 P354, P355 P356, P357 P358, P359 P360, P361 P362, P363 P364, P365 P367, P366 P368, P369 P371, P370 P372, P373 P375, P374 P376, P377 P379, P378 P380, P381 P382, P383 P384, P385 P386, P387 P388, P390 P413, P391 P392, P393 P394, P395 P396, P397 P398, P399 P400, P401 P402, P403 P404, P405 P406, P407 P408, P409 P410, P411 P412, P414 P416, P415 P477, P417 P418, P419 P420, P421 P422, P423 P424, P425 P427, P426 P428, P429 P431, P430 P432, P433 P434, P435 P436, P437 P438, P439 P440, P441 P443, P442 P444, P445 P447, P446 P448, P449 P450, P451 P452, P453 P454, P455 P456, P457 P459, P458 P460, P461 P463, P462 P464, P465 P466, P467 P468, P469 P470, P471 P472, P473 P475, P474 P476, P478 P480, P479 P541, P481 P482, P483 P484, P485 P486, P487 P488, P489 P491, P490 P492, P493 P495, P494 P496, P497 P498, P499 P500, P501 P502, P503 P504, P505 P507, P506 P508, P509 P511, P510 P512, P513 P514, P515 P516, P517 P518, P519 P520, P521 P523, P522 P524, P525 P527, P526 P528, P529 P530, P531 P532, P533 P534, P535 P536, P537 P539, P538 P540, P542 P565, P543 P544, P545 P546, P547 P548, P549 P550, P551 P552, P553 P554, P555 P556, P557 P558, P559 P560, P561 P562, P563 P564, P131 P129
  Pad1: profile Sketch1, direction (1, 0, 0), length 220, mirrored extent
